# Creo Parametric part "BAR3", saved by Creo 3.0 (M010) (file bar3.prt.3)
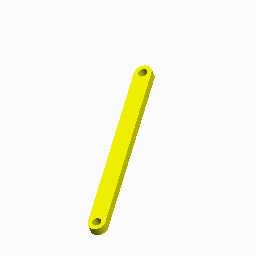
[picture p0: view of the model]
Units: millimeter Newton Second (mmNs); MM, TONNE, SECS

Created from: MMNS_PART_SOLID.PRT

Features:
  1. datum plane "RIGHT"
  2. datum plane "TOP"
  3. datum plane "FRONT"
  4. coordinate system
  5. sketch "Sketch 1"
  6. extrusion "Extrude 1"

Surfaces: 7 plane, 6 cylinder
